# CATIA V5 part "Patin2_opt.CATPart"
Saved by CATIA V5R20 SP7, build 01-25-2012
Part number: Patin2
Bounding box of the stored display mesh (mm): x 0 to 20, y -5.97 to 52.792, z 16.039 to 116.99
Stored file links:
  J:\piece modifiée\Patin2 modif.CATPart
  C:\Users\Cedric\Desktop\ifma\Fichier S3\IAO\IAO refait\cmilovidof.CATProduct
  C:\Users\Cedric\Desktop\ifma\Fichier S3\IAO\Squelette projet IAO\Patin2.CATPart
  C:\Users\Cedric\Desktop\ifma\Fichier S3\IAO\IAO refait\Equerre6.CATPart
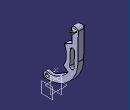
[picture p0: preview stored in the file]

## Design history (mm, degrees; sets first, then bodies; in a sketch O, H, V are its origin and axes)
External parameters (linked from other documents)
  External.diam_roue = 64 mm
Set1
  Plane1: linked copy from another document
  Line1 "Axe_Patin2Equerre6": linked copy from another document
  Line2 "Axe_Patin2Patin1": linked copy from another document
  Point1: linked copy from another document
  Plane2: linked copy from another document
Body1 (main body)
  Sketch1 on Plane2, origin (15, 0, 0), H (0, 1, 0), V (0, 0, 1)
    point P1 (0.5946, 67.9962)
    point P2 (0.5946, 67.9962)
    point P3 (4.3967, 26.0828)
    point P4 (4.3967, 26.0828)
    arc A1 centre (0.5946, 67.9962) radius 51.6165 from (2.1632, 16.4035) to (52.2068, 67.3289) ccw
    line L1 (52.2068, 67.3289) -> (52.7916, 112.5675)
    point P5 (52.2068, 67.3289)
    point P6 (52.2068, 67.3289)
    point P7 (52.7916, 112.5675)
    point P8 (52.7916, 112.5675)
    construction line L2 through (-0.3455, 4.2764) direction (0.0129, 0.9999)
    construction line L3 (0.5946, 67.9962) -> (0, 22)
    construction circle A2 centre (0.5946, 67.9962) radius 32
    arc A3 centre (0.5946, 67.9962) radius 32 from (27.2046, 50.2222) to (28.9219, 82.8813) ccw
    construction line L4 (27.2046, 50.2222) -> (0.5946, 67.9962)
    line L5 (27.2046, 50.2222) -> (35.5912, 44.6204)
    line L6 (28.9219, 82.8813) -> (41.8719, 89.6862)
    axis line L7 (0.5946, 67.9962) -> (28.9219, 82.8813)
    construction line L8 (42.1027, 107.5336) -> (41.4616, 57.9422)
    line L9 (42.1027, 107.5336) -> (41.8719, 89.6862)
    point P9 (35.5912, 44.6204)
    point P10 (35.5912, 44.6204)
    arc A4 centre (47, 111) radius 6 from (52.7916, 112.5675) to (42.1027, 107.5336) ccw
    arc A5 centre (0, 22) radius 6 from (4.3967, 26.0828) to (2.1632, 16.4035) ccw
    point P11 (0, 0)
    construction line L10 through (0, 0) direction (1, 0)
    point P13 (0, 22)
    construction arc A6 centre (0.5946, 67.9962) radius 42.0855 from (4.3967, 26.0828) to (41.4616, 57.9422) ccw
    arc A7 centre (0.5946, 67.9962) radius 42.0855 from (4.3967, 26.0828) to (35.5912, 44.6204) ccw
    reference projected point E1 (0, 22) from Line2
    reference projected point E2 (47, 111) from Line1
    angle L3 L5 = 57
    angle L5 L6 = 61.4613
    radius A3 = 32 {= 32*External.diam_roue /64}
    radius A4 = 6 {= 6*External.diam_roue /64}
    radius A5 = 6 {= 6*External.diam_roue /64}
    distance P13 P1 = 46 {= 46*External.diam_roue /64}
    distance L9 L1 = 10.623 {= 10.623*External.diam_roue /64}
    distance A7 A1 = 9.531 {= 9.531*External.diam_roue /64}
    coincidence: P2 P1, P4 P3, P6 P5, P8 P7, A3 A2, P10 P9
    tangency: L1 A1
    vertical: L3 L2, L1 L2, L9 L2
    parallelism: L5 L4, L7 L6, L8 L1
    concentricity: E1 A5, E2 A4
  Pad1: profile Sketch1, direction (-1, 0, 0), length 10
  Sketch2 on start face of Pad1, origin (15, 0, 0), H (0, 1, 0), V (0, 0, 1)
    circle A1 centre (47, 111) radius 3
    reference projected arc E1 centre (47, 111) radius 6 from (52.7916, 112.5675) to (42.1027, 107.5336) ccw from edge [face of Pad1 from Sketch1.A4 | start face of Pad1]
    radius A1 = 3 {= 3*External.diam_roue /64}
    concentricity: E1 A1
  Pad2: profile Sketch2, direction (1, 0, 0), length 5
  Sketch3 on end face of Pad1, origin (5, 0, 0), H (0, -1, 0), V (0, 0, 1)
    line L1 (-10, 32) -> (10, 32)
    line L2 (10, 32) -> (10, 12)
    line L3 (10, 12) -> (-10, 12)
    line L4 (-10, 12) -> (-10, 32)
    reference projected point E1 (0, 22) from Point1
    reference projected point E2 (0, 22) from Point1
    length L2 = 20
    length L1 = 20
    distance E1 L2 = 10
    distance L3 E2 = 10
    horizontal: L1 H, L3 H
    vertical: L2 V, L4 V
  Pocket1: profile Sketch3, direction (1, 0, 0), length 5
  Sketch4 on end face of Pocket1, origin (10, -0.7241, 17.9456), H (0, 1, 0), V (0, 0, -1)
    point P1 (0.7241, -4.0544)
    reference projected arc E1 centre (0.7241, -4.0544) radius 6 from (2.8873, 1.542) to (5.1208, -8.1372) ccw from edge [face of Pad1 from Sketch1.A5 | end face of Pocket1]
    concentricity: E1 P1
  Hole1: placed by Sketch4, at (10, 0, 22) direction (1, 0, 0), diameter 6 {= 6*External.diam_roue /64}, through (limit type 6)
  Sketch5 on Plane2, origin (15, 0, 0), H (0, 1, 0), V (0, 0, 1)
    construction line L1 (43, 80) -> (42, 55)
    line L2 (46.4972, 79.8601) -> (45.4972, 54.8601)
    line L3 (38.5028, 55.1399) -> (39.5028, 80.1399)
    arc A1 centre (42, 55) radius 3.5 from (45.4972, 54.8601) to (38.5028, 55.1399) cw
    arc A2 centre (43, 80) radius 3.5 from (39.5028, 80.1399) to (46.4972, 79.8601) cw
    distance L1 L2 = 3.5
    tangency: A1 L2, A2 L2, A1 L3, A2 L3
  Pocket2: profile Sketch5, direction (-1, 0, 0), through (limit type 6)
  Chamfer1: length 8.5, angle 30, on edge [end face of Pad1 | face of Pocket1 from Sketch3.L4]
